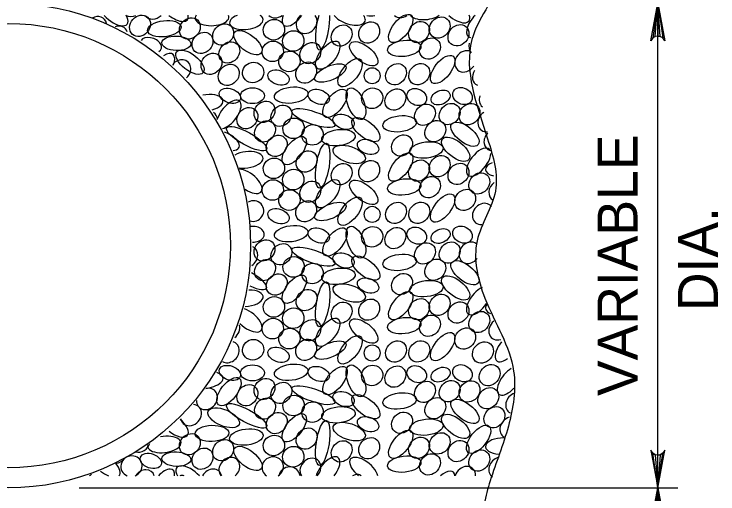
# Model space of a CAD drawing. Extents: x 1.32 to 7.47, y -3.56 to 5.14.
# Drawn here: x 3.855 to 4.912, y -0.701 to 0.019 of the extents above; entities that cross this region are included whole.
import ezdxf

# ---------------------------------------------------------------- set-up
doc = ezdxf.new("R2010")
doc.units = 0
for name, color, linetype in [('DETL-DIMS', 7, 'Continuous'), ('DETL-LINE', 7, 'Continuous'), ('DETL-NOTE', 7, 'Continuous'), ('DETL-PATT', 7, 'Continuous')]:
    doc.layers.add(name, color=color, linetype=linetype)

msp = doc.modelspace()

# ---------------------------------------------------------------- linework, layer by layer
at = {"layer": 'DETL-DIMS'}
for p, q in [((4.8221, -0.6917), (4.8221, 0.0356)), ((3.9532, -0.6917), (4.8524, -0.6917)), ((4.8221, -0.9341), (4.8221, -0.6917))]:
    msp.add_line(p, q, dxfattribs=at)
for points in [[(4.8221, 0.0356), (4.8327, -0.0209), (4.8297, -0.0165), (4.8259, -0.0143), (4.8221, -0.0136), (4.8184, -0.0143), (4.8146, -0.0165), (4.8116, -0.0209), (4.8221, 0.0356), (4.8146, -0.0165), (4.8184, -0.0143), (4.8221, 0.0356), (4.8221, -0.0136), (4.8259, -0.0143), (4.8221, 0.0356), (4.8297, -0.0165)], [(4.8221, -0.6917), (4.8327, -0.6352), (4.8297, -0.6395), (4.8259, -0.6418), (4.8221, -0.6424), (4.8184, -0.6418), (4.8146, -0.6395), (4.8116, -0.6352), (4.8221, -0.6917), (4.8146, -0.6395), (4.8184, -0.6418), (4.8221, -0.6917), (4.8221, -0.6424), (4.8259, -0.6418), (4.8221, -0.6917), (4.8297, -0.6395)], [(4.8221, -0.6917), (4.8327, -0.7482), (4.8297, -0.7438), (4.8259, -0.7416), (4.8221, -0.7409), (4.8184, -0.7416), (4.8146, -0.7438), (4.8116, -0.7482), (4.8221, -0.6917), (4.8146, -0.7438), (4.8184, -0.7416), (4.8221, -0.6917), (4.8221, -0.7409), (4.8259, -0.7416), (4.8221, -0.6917), (4.8297, -0.7438)]]:
    msp.add_lwpolyline(points, dxfattribs=at)
at = {"layer": 'DETL-LINE'}
for radius in [0.3636, 0.3333]:
    msp.add_circle((3.8471, -0.328), radius, dxfattribs=at)
msp.add_spline([(4.6047, 0.8841), (4.5978, 0.8549), (4.5822, 0.8236), (4.5548, 0.7374), (4.5939, 0.6551), (4.5978, 0.5924), (4.5978, 0.5022), (4.59, 0.4199), (4.5744, 0.322), (4.59, 0.2357), (4.6096, 0.1456), (4.59, 0.0712), (4.543, -0.019), (4.5665, -0.1679), (4.5783, -0.2463), (4.5509, -0.3207), (4.5626, -0.4069), (4.6057, -0.5167), (4.5978, -0.599), (4.5704, -0.6812), (4.5626, -0.7518), (4.59, -0.8615), (4.5822, -0.8733), (4.5744, -0.9341)], degree=3, dxfattribs=at)
at = {"layer": 'DETL-PATT'}
for centre, major_axis, ratio in [((4.4362, -0.0023), (-0.0156, -0.0199), 0.479042), ((4.0446, 0.0017), (0.0114, 0.0128), 0.844245), ((4.0811, -0.0026), (-0.0251, -0.003), 0.479042), ((4.1194, -0.0023), (0.0114, 0.0128), 0.844245), ((4.2457, -0.0041), (0.015, 0.006), 0.948581), ((4.4945, -0.0009), (0.0114, 0.0128), 0.844245), ((4.1694, -0.0113), (0.0114, 0.0128), 0.844245), ((4.3474, -0.0129), (0.0114, 0.0128), 0.844245), ((4.3887, -0.0083), (0.0114, 0.0128), 0.844245), ((4.4636, -0.0076), (0.0114, 0.0128), 0.844245), ((4.5228, -0.0125), (0.0114, 0.0128), 0.844245), ((4.1384, -0.0239), (0.0114, 0.0128), 0.844245), ((4.2066, -0.0236), (-0.0199, 0.0156), 0.479042), ((4.2748, -0.021), (0.015, 0.006), 0.948581), ((4.0991, -0.0245), (0.0217, -0.0009), 0.504072), ((4.1787, -0.0381), (0.0114, 0.0128), 0.844245), ((4.2439, -0.0366), (0.015, 0.006), 0.948581), ((4.3005, -0.0392), (0.0114, 0.0128), 0.844245), ((4.3266, -0.0423), (-0.0156, -0.0199), 0.479042), ((4.3806, -0.0402), (-0.0199, 0.0156), 0.479042), ((4.4414, -0.0321), (-0.0251, -0.003), 0.479042), ((4.48, -0.0324), (0.0114, 0.0128), 0.844245), ((4.1196, -0.0529), (-0.0199, 0.0156), 0.479042), ((4.1519, -0.0554), (0.0114, 0.0128), 0.844245), ((4.2689, -0.0517), (0.015, 0.006), 0.948581), ((4.4991, -0.0638), (-0.0156, -0.0199), 0.479042), ((4.2144, -0.0683), (0.015, 0.006), 0.948581), ((4.2941, -0.0685), (0.0114, 0.0128), 0.844245), ((4.3601, -0.0686), (-0.0156, -0.0199), 0.479042), ((4.4639, -0.0709), (0.0114, 0.0128), 0.844245), ((4.1779, -0.0719), (0.0114, 0.0128), 0.844245), ((4.2526, -0.0759), (0.0156, -0.0055), 0.646802), ((4.3304, -0.069), (-0.0232, -0.0098), 0.422273), ((4.3933, -0.0732), (0, 0.0121), 0.982495), ((4.429, -0.071), (0.0114, 0.0128), 0.844245), ((4.1796, -0.1033), (0.0156, -0.0055), 0.646802), ((4.2135, -0.1031), (0.0178, 0), 0.671766), ((4.2716, -0.1023), (-0.0251, -0.003), 0.479042), ((4.313, -0.1048), (0.0156, -0.0055), 0.646802), ((4.3374, -0.1146), (-0.0156, -0.0199), 0.479042), ((4.3689, -0.1151), (0.0094, -0.0235), 0.479042), ((4.3933, -0.107), (0.015, 0.006), 0.948581), ((4.4281, -0.1088), (0.0114, 0.0128), 0.844245), ((4.4602, -0.1051), (0.0136, -0.007), 0.796199), ((4.496, -0.1058), (-0.0136, -0.0061), 0.687276), ((4.5289, -0.1036), (0.0136, -0.007), 0.796199), ((4.2315, -0.1274), (0.0114, 0.0128), 0.844245), ((4.2569, -0.1332), (0.0114, 0.0128), 0.844245), ((4.4725, -0.1317), (0.0114, 0.0128), 0.844245), ((4.5095, -0.1306), (0.0114, 0.0128), 0.844245), ((4.5394, -0.1308), (0.0114, 0.0128), 0.844245), ((4.2058, -0.1368), (0.0114, 0.0128), 0.844245), ((4.3051, -0.1367), (0.0323, -0.0109), 0.282192), ((4.2753, -0.1521), (0.015, 0.006), 0.948581), ((4.3503, -0.1423), (0.0156, -0.0055), 0.646802), ((4.3837, -0.1539), (-0.0199, 0.0156), 0.479042), ((4.4345, -0.1453), (-0.0251, -0.003), 0.479042), ((4.2046, -0.1675), (0.0299, -0.0164), 0.282192), ((4.2324, -0.1567), (0.0114, 0.0128), 0.844245), ((4.3038, -0.1619), (0.015, 0.006), 0.948581), ((4.488, -0.1563), (0.0114, 0.0128), 0.844245), ((4.5326, -0.1609), (-0.0199, 0.0156), 0.479042), ((4.3426, -0.1661), (-0.0251, -0.003), 0.479042), ((4.2499, -0.1784), (0.0114, 0.0128), 0.844245), ((4.2762, -0.1855), (-0.0156, -0.0199), 0.479042), ((4.387, -0.18), (0.0156, -0.0055), 0.646802), ((4.4381, -0.1778), (0.0114, 0.0128), 0.844245), ((4.5186, -0.1835), (-0.0199, 0.0156), 0.479042), ((4.3189, -0.2083), (0.0052, 0.0337), 0.282192), ((4.3587, -0.1913), (-0.024, 0.0079), 0.479042), ((4.4746, -0.1846), (-0.0251, -0.003), 0.479042), ((4.2947, -0.2018), (0.0114, 0.0128), 0.844245), ((4.4362, -0.2103), (-0.0156, -0.0199), 0.479042), ((4.2457, -0.2121), (0.015, 0.006), 0.948581), ((4.3887, -0.2163), (0.0114, 0.0128), 0.844245), ((4.4636, -0.2156), (0.0114, 0.0128), 0.844245), ((4.4945, -0.2089), (0.0114, 0.0128), 0.844245), ((4.3474, -0.2208), (0.0114, 0.0128), 0.844245), ((4.5228, -0.2205), (0.0114, 0.0128), 0.844245), ((4.2748, -0.229), (0.015, 0.006), 0.948581), ((4.5541, -0.2347), (0.0114, 0.0128), 0.844245), ((4.2439, -0.2446), (0.015, 0.006), 0.948581), ((4.3005, -0.2472), (0.0114, 0.0128), 0.844245), ((4.3266, -0.2502), (-0.0156, -0.0199), 0.479042), ((4.3806, -0.2482), (-0.0199, 0.0156), 0.479042), ((4.4414, -0.2401), (-0.0251, -0.003), 0.479042), ((4.48, -0.2404), (0.0114, 0.0128), 0.844245), ((4.2689, -0.2597), (0.015, 0.006), 0.948581), ((4.5329, -0.2595), (0.0114, 0.0128), 0.844245), ((4.3601, -0.2765), (-0.0156, -0.0199), 0.479042), ((4.4991, -0.2717), (-0.0156, -0.0199), 0.479042), ((4.2941, -0.2765), (0.0114, 0.0128), 0.844245), ((4.3304, -0.2769), (-0.0232, -0.0098), 0.422273), ((4.429, -0.279), (0.0114, 0.0128), 0.844245), ((4.4639, -0.2789), (0.0114, 0.0128), 0.844245), ((4.2526, -0.2839), (0.0156, -0.0055), 0.646802), ((4.3933, -0.2812), (0, 0.0121), 0.982495), ((4.2716, -0.3102), (-0.0251, -0.003), 0.479042), ((4.313, -0.3128), (0.0156, -0.0055), 0.646802), ((4.3374, -0.3226), (-0.0156, -0.0199), 0.479042), ((4.3689, -0.323), (0.0094, -0.0235), 0.479042), ((4.3933, -0.3149), (0.015, 0.006), 0.948581), ((4.4281, -0.3167), (0.0114, 0.0128), 0.844245), ((4.4602, -0.3131), (0.0136, -0.007), 0.796199), ((4.496, -0.3137), (-0.0136, -0.0061), 0.687276), ((4.5289, -0.3116), (0.0136, -0.007), 0.796199), ((4.2315, -0.3353), (0.0114, 0.0128), 0.844245), ((4.2569, -0.3411), (0.0114, 0.0128), 0.844245), ((4.4725, -0.3397), (0.0114, 0.0128), 0.844245), ((4.5095, -0.3386), (0.0114, 0.0128), 0.844245), ((4.3051, -0.3446), (0.0323, -0.0109), 0.282192), ((4.3503, -0.3503), (0.0156, -0.0055), 0.646802), ((4.2324, -0.3647), (0.0114, 0.0128), 0.844245), ((4.2753, -0.3601), (0.015, 0.006), 0.948581), ((4.3837, -0.3619), (-0.0199, 0.0156), 0.479042), ((4.4345, -0.3533), (-0.0251, -0.003), 0.479042), ((4.488, -0.3642), (0.0114, 0.0128), 0.844245), ((4.5326, -0.3689), (-0.0199, 0.0156), 0.479042), ((4.3038, -0.3699), (0.015, 0.006), 0.948581), ((4.2499, -0.3864), (0.0114, 0.0128), 0.844245), ((4.2762, -0.3935), (-0.0156, -0.0199), 0.479042), ((4.3426, -0.3741), (-0.0251, -0.003), 0.479042), ((4.4381, -0.3858), (0.0114, 0.0128), 0.844245), ((4.387, -0.3879), (0.0156, -0.0055), 0.646802), ((4.4746, -0.3926), (-0.0251, -0.003), 0.479042), ((4.5186, -0.3915), (-0.0199, 0.0156), 0.479042), ((4.3189, -0.4163), (0.0052, 0.0337), 0.282192), ((4.3587, -0.3992), (-0.024, 0.0079), 0.479042), ((4.2947, -0.4098), (0.0114, 0.0128), 0.844245), ((4.4362, -0.4183), (-0.0156, -0.0199), 0.479042), ((4.4945, -0.4169), (0.0114, 0.0128), 0.844245), ((4.2457, -0.4201), (0.015, 0.006), 0.948581), ((4.3474, -0.4288), (0.0114, 0.0128), 0.844245), ((4.3887, -0.4242), (0.0114, 0.0128), 0.844245), ((4.4636, -0.4236), (0.0114, 0.0128), 0.844245), ((4.5228, -0.4284), (0.0114, 0.0128), 0.844245), ((4.2748, -0.437), (0.015, 0.006), 0.948581), ((4.48, -0.4483), (0.0114, 0.0128), 0.844245), ((4.5541, -0.4427), (0.0114, 0.0128), 0.844245), ((4.2439, -0.4526), (0.015, 0.006), 0.948581), ((4.3005, -0.4551), (0.0114, 0.0128), 0.844245), ((4.3266, -0.4582), (-0.0156, -0.0199), 0.479042), ((4.3806, -0.4562), (-0.0199, 0.0156), 0.479042), ((4.4414, -0.4481), (-0.0251, -0.003), 0.479042), ((4.2689, -0.4676), (0.015, 0.006), 0.948581), ((4.5329, -0.4675), (0.0114, 0.0128), 0.844245), ((4.3601, -0.4845), (-0.0156, -0.0199), 0.479042), ((4.4991, -0.4797), (-0.0156, -0.0199), 0.479042), ((4.2144, -0.4843), (0.015, 0.006), 0.948581), ((4.2941, -0.4844), (0.0114, 0.0128), 0.844245), ((4.3304, -0.4849), (-0.0232, -0.0098), 0.422273), ((4.429, -0.487), (0.0114, 0.0128), 0.844245), ((4.4639, -0.4868), (0.0114, 0.0128), 0.844245), ((4.5595, -0.4885), (0.0114, 0.0128), 0.844245), ((4.2526, -0.4918), (0.0156, -0.0055), 0.646802), ((4.3933, -0.4892), (0, 0.0121), 0.982495), ((4.1796, -0.5192), (0.0156, -0.0055), 0.646802), ((4.2135, -0.5191), (0.0178, 0), 0.671766), ((4.2716, -0.5182), (-0.0251, -0.003), 0.479042), ((4.3374, -0.5306), (-0.0156, -0.0199), 0.479042), ((4.3689, -0.531), (0.0094, -0.0235), 0.479042), ((4.3933, -0.5229), (0.015, 0.006), 0.948581), ((4.4281, -0.5247), (0.0114, 0.0128), 0.844245), ((4.4602, -0.521), (0.0136, -0.007), 0.796199), ((4.5289, -0.5196), (0.0136, -0.007), 0.796199), ((4.5696, -0.5224), (0.0114, 0.0128), 0.844245), ((4.313, -0.5207), (0.0156, -0.0055), 0.646802), ((4.496, -0.5217), (-0.0136, -0.0061), 0.687276), ((4.1781, -0.5471), (-0.0156, -0.0199), 0.479042), ((4.2315, -0.5433), (0.0114, 0.0128), 0.844245), ((4.5095, -0.5465), (0.0114, 0.0128), 0.844245), ((4.2058, -0.5527), (0.0114, 0.0128), 0.844245), ((4.2569, -0.5491), (0.0114, 0.0128), 0.844245), ((4.3051, -0.5526), (0.0323, -0.0109), 0.282192), ((4.4725, -0.5476), (0.0114, 0.0128), 0.844245), ((4.5394, -0.5468), (0.0114, 0.0128), 0.844245), ((4.3503, -0.5583), (0.0156, -0.0055), 0.646802), ((4.3837, -0.5699), (-0.0199, 0.0156), 0.479042), ((4.4345, -0.5612), (-0.0251, -0.003), 0.479042), ((4.5676, -0.5572), (0.0114, 0.0128), 0.844245), ((4.2324, -0.5727), (0.0114, 0.0128), 0.844245), ((4.2753, -0.5681), (0.015, 0.006), 0.948581), ((4.488, -0.5722), (0.0114, 0.0128), 0.844245), ((4.5326, -0.5769), (-0.0199, 0.0156), 0.479042), ((4.1701, -0.5864), (-0.0233, 0.01), 0.479042), ((4.2046, -0.5835), (0.0299, -0.0164), 0.282192), ((4.3038, -0.5779), (0.015, 0.006), 0.948581), ((4.3426, -0.582), (-0.0251, -0.003), 0.479042), ((4.5768, -0.5857), (0.0114, 0.0128), 0.844245), ((4.2499, -0.5943), (0.0114, 0.0128), 0.844245), ((4.2762, -0.6014), (-0.0156, -0.0199), 0.479042), ((4.4381, -0.5938), (0.0114, 0.0128), 0.844245), ((4.5186, -0.5994), (-0.0199, 0.0156), 0.479042), ((4.3189, -0.6243), (0.0052, 0.0337), 0.282192), ((4.3587, -0.6072), (-0.024, 0.0079), 0.479042), ((4.387, -0.5959), (0.0156, -0.0055), 0.646802), ((4.4746, -0.6005), (-0.0251, -0.003), 0.479042), ((4.1527, -0.6098), (-0.0253, -0.0008), 0.479042), ((4.2043, -0.6153), (-0.0251, -0.003), 0.479042), ((4.2947, -0.6177), (0.0114, 0.0128), 0.844245), ((4.4362, -0.6262), (-0.0156, -0.0199), 0.479042), ((4.553, -0.6187), (-0.0156, -0.0199), 0.479042), ((4.1194, -0.6262), (0.0114, 0.0128), 0.844245), ((4.2457, -0.628), (0.015, 0.006), 0.948581), ((4.4945, -0.6248), (0.0114, 0.0128), 0.844245), ((4.1694, -0.6352), (0.0114, 0.0128), 0.844245), ((4.3474, -0.6368), (0.0114, 0.0128), 0.844245), ((4.3887, -0.6322), (0.0114, 0.0128), 0.844245), ((4.4636, -0.6315), (0.0114, 0.0128), 0.844245), ((4.5228, -0.6364), (0.0114, 0.0128), 0.844245), ((4.1384, -0.6478), (0.0114, 0.0128), 0.844245), ((4.2066, -0.6475), (-0.0199, 0.0156), 0.479042), ((4.2748, -0.6449), (0.015, 0.006), 0.948581), ((4.5541, -0.6506), (0.0114, 0.0128), 0.844245), ((4.0609, -0.6512), (0.0156, -0.0055), 0.646802), ((4.0991, -0.6484), (0.0217, -0.0009), 0.504072), ((4.4414, -0.656), (-0.0251, -0.003), 0.479042), ((4.48, -0.6563), (0.0114, 0.0128), 0.844245)]:
    msp.add_ellipse(centre, major_axis=major_axis, ratio=ratio, dxfattribs=at)
for centre, major_axis, ratio, start_param, end_param in [((3.9787, -0.0002), (0.0114, 0.0128), 0.844245, 5.714817, 7.480472), ((4.0054, 0.02), (-0.0199, 0.0156), 0.479042, 1.162781, 4.025346), ((4.0334, 0.0315), (0.0114, 0.0128), 0.844245, 3.285362, 4.285477), ((4.0643, 0.0274), (0.015, 0.006), 0.948581, 3.442092, 5.184667), ((4.096, 0.0266), (-0.0199, 0.0156), 0.479042, 1.546733, 3.641394), ((4.1527, 0.0141), (-0.0253, -0.0008), 0.479042, 5.935184, 9.638586), ((4.2043, 0.0086), (-0.0251, -0.003), 0.479042, 5.246446, 9.970552), ((4.2499, 0.0296), (0.0114, 0.0128), 0.844245, 3.076634, 4.494205), ((4.2762, 0.0225), (-0.0156, -0.0199), 0.479042, 5.312442, 7.973883), ((4.2947, 0.0062), (0.0114, 0.0128), 0.844245, 1.434862, 6.135977), ((4.3189, -0.0004), (0.0052, 0.0337), 0.282192, 1.059138, 5.310248), ((4.3587, 0.0167), (-0.024, 0.0079), 0.479042, 0.548579, 3.793604), ((4.387, 0.028), (0.0156, -0.0055), 0.646802, 4.810981, 5.612785), ((4.4381, 0.0301), (0.0114, 0.0128), 0.844245, 3.134069, 4.43677), ((4.4746, 0.0234), (-0.0251, -0.003), 0.479042, 0.252476, 2.398151), ((4.5186, 0.0245), (-0.0199, 0.0156), 0.479042, 1.41723, 3.770897), ((4.553, 0.0052), (-0.0156, -0.0199), 0.479042, 4.458843, 6.583728), ((4.0104, -0.0146), (0.0114, 0.0128), 0.844245, 5.828563, 7.286305), ((4.0609, -0.0273), (0.0156, -0.0055), 0.646802, 5.789091, 9.260235), ((4.5541, -0.0267), (0.0114, 0.0128), 0.844245, 2.079957, 3.054082), ((4.0784, -0.0609), (-0.0156, -0.0199), 0.479042, 2.106567, 4.092645), ((4.5329, -0.0516), (0.0114, 0.0128), 0.844245, 0.233828, 4.900211), ((4.1051, -0.0652), (0.0114, 0.0128), 0.844245, 4.596713, 7.90804), ((4.5595, -0.0726), (0.0114, 0.0128), 0.844245, 1.741253, 3.398973), ((4.1441, -0.1137), (-0.0251, -0.003), 0.479042, 1.867806, 4.871503), ((4.5696, -0.1065), (0.0114, 0.0128), 0.844245, 2.019598, 3.183561), ((4.1781, -0.1311), (-0.0156, -0.0199), 0.479042, 0.458653, 5.42705), ((4.1452, -0.1422), (0.0114, 0.0128), 0.844245, 5.564347, 6.426399), ((4.5676, -0.1413), (0.0114, 0.0128), 0.844245, 1.264403, 3.89382), ((4.1701, -0.1705), (-0.0233, 0.01), 0.479042, 2.416186, 4.851538), ((4.5768, -0.1698), (0.0114, 0.0128), 0.844245, 1.48895, 3.553563), ((4.553, -0.2028), (-0.0156, -0.0199), 0.479042, 2.852782, 8.854486), ((4.2043, -0.1994), (-0.0251, -0.003), 0.479042, 1.06215, 5.425132), ((4.5887, -0.213), (-0.0253, -0.0008), 0.479042, 5.35588, 7.280176), ((4.2066, -0.2316), (-0.0199, 0.0156), 0.479042, 1.73508, 5.71709), ((4.5841, -0.2457), (0.0114, 0.0128), 0.844245, 1.330535, 3.313327), ((4.2144, -0.2763), (0.015, 0.006), 0.948581, 4.016595, 7.961332), ((4.5595, -0.2806), (0.0114, 0.0128), 0.844245, 6.136816, 10.125412), ((4.2135, -0.3111), (0.0178, 0), 0.671766, 4.700458, 8.044466), ((4.5394, -0.3388), (0.0114, 0.0128), 0.844245, 6.274141, 11.056218), ((4.2058, -0.3447), (0.0114, 0.0128), 0.844245, 4.410371, 6.53553), ((4.2046, -0.3755), (0.0299, -0.0164), 0.282192, 5.024645, 7.753695), ((4.553, -0.4108), (-0.0156, -0.0199), 0.479042, 3.853561, 8.015906), ((4.2043, -0.4073), (-0.0251, -0.003), 0.479042, 1.436141, 4.508384), ((4.5887, -0.421), (-0.0253, -0.0008), 0.479042, 5.843136, 7.067491), ((4.2066, -0.4395), (-0.0199, 0.0156), 0.479042, 1.331635, 5.310446), ((4.5841, -0.4536), (0.0114, 0.0128), 0.844245, 1.374646, 4.088621), ((4.1787, -0.454), (0.0114, 0.0128), 0.844245, 4.491889, 5.789933), ((4.1779, -0.4878), (0.0114, 0.0128), 0.844245, 3.326268, 6.676761), ((4.5962, -0.4812), (-0.0156, -0.0199), 0.479042, 4.66046, 7.326959), ((4.5992, -0.5313), (-0.0156, -0.0199), 0.479042, 4.006318, 7.674085), ((4.1441, -0.5296), (-0.0251, -0.003), 0.479042, 1.514671, 3.967545), ((4.1452, -0.5582), (0.0114, 0.0128), 0.844245, 2.347631, 7.216059), ((4.6095, -0.5648), (0.0114, 0.0128), 0.844245, 0.988738, 3.330325), ((4.1213, -0.5824), (0.0114, 0.0128), 0.844245, 2.560199, 6.874967), ((4.096, -0.5973), (-0.0199, 0.0156), 0.479042, 1.560646, 4.643704), ((4.6007, -0.6011), (0.0114, 0.0128), 0.844245, 0.934895, 3.324012), ((4.0811, -0.6265), (-0.0251, -0.003), 0.479042, 6.063516, 11.169969), ((4.5887, -0.6289), (-0.0253, -0.0008), 0.479042, 4.602035, 7.641711), ((4.0446, -0.6222), (0.0114, 0.0128), 0.844245, 3.530977, 5.185561), ((4.0318, -0.6591), (0.015, 0.006), 0.948581, 4.69243, 10.217515), ((4.3266, -0.6662), (-0.0156, -0.0199), 0.479042, 1.580088, 5.423052), ((4.3806, -0.6641), (-0.0199, 0.0156), 0.479042, 3.629953, 7.84136), ((3.9935, -0.6574), (-0.0199, 0.0156), 0.479042, 3.089552, 4.307117), ((4.0104, -0.6385), (0.0114, 0.0128), 0.844245, 3.842293, 4.823647), ((4.1787, -0.662), (0.0114, 0.0128), 0.844245, 4.552127, 9.301898), ((4.2439, -0.6605), (0.015, 0.006), 0.948581, 4.888786, 10.021158), ((4.3005, -0.6631), (0.0114, 0.0128), 0.844245, 4.650828, 9.203196), ((4.5841, -0.6616), (0.0114, 0.0128), 0.844245, 0.937793, 3.239335), ((4.0509, -0.6804), (0.0114, 0.0128), 0.844245, 5.806132, 8.047892), ((4.0784, -0.6848), (-0.0156, -0.0199), 0.479042, 2.493495, 4.509645), ((4.1196, -0.6768), (-0.0199, 0.0156), 0.479042, 4.347351, 7.123961), ((4.1519, -0.6793), (0.0114, 0.0128), 0.844245, 5.726241, 8.127784), ((4.2689, -0.6756), (0.015, 0.006), 0.948581, 6.022457, 8.887488), ((4.5329, -0.6755), (0.0114, 0.0128), 0.844245, 5.480542, 8.373482), ((3.9612, -0.6616), (-0.0148, -0.0059), 0.87402, 1.723329, 1.994418), ((3.9935, -0.6574), (-0.0199, 0.0156), 0.479042, 1.535109, 2.098576), ((4.1051, -0.6891), (0.0114, 0.0128), 0.844245, 0.431043, 0.856611), ((4.3601, -0.6925), (-0.0156, -0.0199), 0.479042, 3.036139, 3.967001), ((4.4991, -0.6877), (-0.0156, -0.0199), 0.479042, 2.661726, 4.341414)]:
    msp.add_ellipse(centre, major_axis=major_axis, ratio=ratio, start_param=start_param, end_param=end_param, dxfattribs=at)

# ---------------------------------------------------------------- texts
at = {"layer": 'DETL-NOTE'}
for s, p in [('VARIABLE', (4.7918, -0.5538)), ('DIA.', (4.9124, -0.4263))]:
    msp.add_text(s, height=0.06, rotation=90, dxfattribs=at).set_placement(p)

doc.saveas('drawing.dxf')
